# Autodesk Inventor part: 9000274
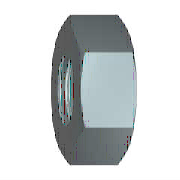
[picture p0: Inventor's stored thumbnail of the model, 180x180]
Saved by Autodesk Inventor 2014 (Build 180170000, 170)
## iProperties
IsCustomPart: 1
Created: 2011-02
Material: Steel, Mild
Description: NUT, HEX 1/2-13
Document SubType Name: Modeling
Standard: AS 2465
Designer: Dave Walker
Standards Organization: AS
Language: en-US
Size Designation: 1/2  UNC
Categories: <MemberInstance><Categories><Category DisplayName="Fasteners" InternalName="e4da775c-781d-43d5-af7c-5136215cf5a6" Mnemonic="FSTN"><Category DisplayName="Nuts" I
Density: 7.86 g/cm^3
Mass: 14.2866 g
Surface Area: 12.0862 cm^2
Volume: 1.81763 cm^3
Part Number: 9000274
Appearance: Steel
Author: Dave Walker
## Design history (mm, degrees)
sketch "Sketch1"
  geometry: L1 (-10.999, 0)-(-5.499, 9.525); L2 (-5.499, 9.525)-(5.499, 9.525); L3 (5.499, 9.525)-(10.999, 0); L4 (10.999, 0)-(5.499, -9.525); L5 (5.499, -9.525)-(-5.499, -9.525); L6 (-5.499, -9.525)-(-10.999, 0); 2 further points
  constraints: 12 end point, 1 coincident, 1 horizontal, 11 other
  dimensions: "d0" = 21.99705 distance of L3.end L1.start (= 1.1547 x SW)
extrude "Body" new body sketch "Sketch1" distance "d1" = 8.2042 (= KOH); taper "d2" = 0 deg
sketch "Sketch2"
  geometry: L1 (0, 5.499)-(0, 10.999) reference; L2 (0, 10.999)-(8.204, 10.999) reference; L3 (8.204, 5.499)-(8.204, 10.999) reference; L4 (-1.641, 0)-(9.845, 0) reference; L5 (0.851, 10.999)-(0, 9.525); L6 (7.353, 10.999)-(8.204, 9.525)
  constraints: 4 end point, 4 point on line
  dimensions: "d3" = 30 deg angle of L1 L5 (= ANG1); "d4" = 30 deg angle of L3 L6 (= ANG2); "d5" = 19.05 diameter of L5.end L4 (= SW0); "d6" = 19.05 diameter of L6.end L4 (= SW01)
revolve "Chamfer1" sketch "Sketch2" stored, may be unused: angle "d7" = 90 deg
sketch "Sketch3"
  geometry: A1 r 9.525 centre (0, 0) between (-4.762, -8.249) and (4.763, -8.249) reference; 1 further point
  constraints: 1 coincident
hole "Thread" sketch "Sketch3" at (0, 0) diameter "d25" = 10.5918; stored, may be unused: countersink angle "d29" = 82 deg, drill point angle "d31" = 118 deg; dims "d26" = 6, "d27" = 4, "d28" = 2, "d30" = 8
workaxis "Work Axis1"
workplane "Work Plane1"
body "Solid1"
chamfer "Chamfer2" distance "d8" = 1.05755 (= -0.5 x GD1 + 0.5 x NND); stored, may be unused: angle "d9" = 30 deg, second distance "d40" = 1.05755 (= -0.5 x GD1 + 0.5 x NND)
chamfer "Chamfer3" distance "d10" = 1.05755 (= -0.5 x GD1 + 0.5 x NND); stored, may be unused: angle "d11" = 30 deg, second distance "d41" = 1.05755 (= -0.5 x GD1 + 0.5 x NND)
other parameters: "ANG1" = 30 deg [user parameter; used in 1 equation term], "ANG2" = 30 deg [user parameter; used in 1 equation term], "NND" = 12.7 [user parameter; used in 4 equation terms], "KOH" = 8.2042 [user parameter; used in 1 equation term], "SW" = 19.05 [user parameter; used in 4 equation terms], "SW0" = 19.05 (= SW) [user parameter; used in 1 equation term], "SW01" = 19.05 (= SW) [user parameter; used in 1 equation term], "GD1" = 10.5849 (computed from THREADDIA, PTC, TOA) [user parameter; used in 4 equation terms], "d13" = 0, "d14" = 0, "d39" = 0, "d42" = 0, "THREADDIA" = 12.7 [user parameter; used in 1 equation term], "TOA" = 30 deg [user parameter; used in 1 equation term], "PTC" = 1.95385 (computed from TPU) [user parameter; used in 1 equation term], "E0" = 22.00275 (= 1.155 x SW) [user parameter]
